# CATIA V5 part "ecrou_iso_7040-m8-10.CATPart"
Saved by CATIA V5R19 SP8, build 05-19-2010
Part number: ecrou_iso_7040-M8-10
Nomenclature: 31
Source: Unknown
Description: PART-ecrou_iso_7040-m8-10-DESC
Bounding box of the stored display mesh (mm): x -7.506 to 7.506, y -6.5 to 6.5, z 0 to 9.5
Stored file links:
  C:\Users\rphgr\Desktop\0_Tapis_TC520B_vitesse\ecrou_iso_7040-m8-10.CATPart
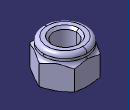
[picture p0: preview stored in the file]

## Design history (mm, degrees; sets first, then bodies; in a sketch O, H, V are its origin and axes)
AxisSystem1: origin (0, 0, 0), X (1, 0, 0), Y (0, 1, 0), Z (0, 0, 1)
Body1 "ecrou_iso_7040-m8-10" (main body)
  Solid1: solid without history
